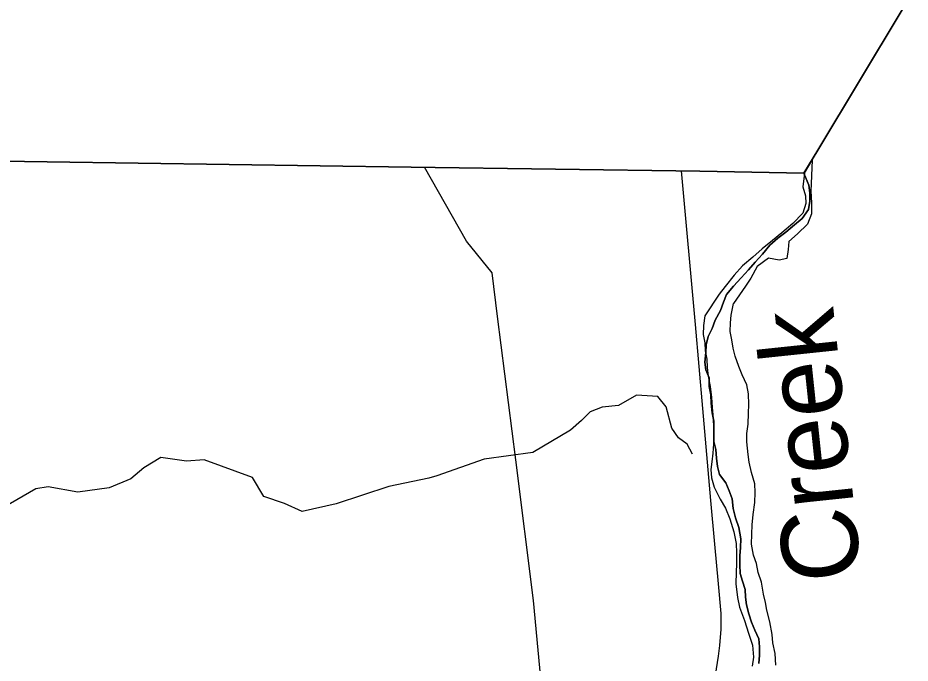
# Model space of a CAD drawing. Extents: x 1525783 to 1900577, y 218250 to 627376.
# Drawn here: x 1716711 to 1722538, y 499637 to 503848 of the extents above; entities that cross this region are included whole.
import ezdxf

# ---------------------------------------------------------------- set-up
doc = ezdxf.new("R2010")
doc.units = 0
for name, color, linetype in [('GM_X_Adjacent_County', 7, 'Continuous'), ('GM_X_County', 7, 'Continuous'), ('GM_X_Major_River', 7, 'Continuous'), ('GM_X_Major_River_Text', 7, 'Continuous'), ('GM_X_Minor_River', 7, 'Continuous'), ('GM_X_Rail_Line', 7, 'Continuous'), ('GM_X_State_Route', 7, 'Continuous'), ('GM_X_Township', 7, 'Continuous')]:
    doc.layers.add(name, color=color, linetype=linetype)

msp = doc.modelspace()

# ---------------------------------------------------------------- linework, layer by layer
at = {"layer": 'GM_X_Adjacent_County'}
for points in [[(1735942.3, 526251.7), (1733055.8, 521469.6), (1733029.3, 521425.7), (1732533.7, 520602.9), (1729525.6, 515601.5), (1727395.9, 512074.5), (1725220.4, 508448.9), (1721934.8, 502985.4), (1721843.8, 502834), (1721165.1, 502848), (1719280.1, 502874.9), (1716306.7, 502917.3), (1714432, 502944), (1711385.6, 502988.7), (1707042.7, 503052.5), (1704565.5, 503089.8), (1704436.7, 503091.7), (1698640.9, 503175.5)], [(1721549.6, 499634), (1721555.2, 499690), (1721554.6, 499744.2), (1721550.1, 499796.4), (1721523.6, 499851.3), (1721503, 499904), (1721484.5, 499958.6), (1721470.1, 500017.2), (1721463.5, 500067.5), (1721460.8, 500117.7), (1721442.3, 500172.3), (1721427.7, 500222.8), (1721425.2, 500279), (1721426.8, 500337.1), (1721430.3, 500391.2), (1721431.9, 500449.3), (1721419.9, 500521.8), (1721397.6, 500584.6), (1721383.3, 500647.1), (1721375, 500709.5), (1721356.4, 500762.1), (1721333.8, 500812.9), (1721293.3, 500868.1), (1721280.7, 500920.6), (1721274.2, 500974.9), (1721269.7, 501031.2), (1721255.2, 501083.7), (1721255.2, 501157.9), (1721256.8, 501216), (1721244.3, 501270.5), (1721238, 501334.8), (1721235.5, 501389), (1721225, 501443.4), (1721226.5, 501499.5), (1721203.9, 501550.3), (1721197.3, 501600.6), (1721203, 501664.6), (1721206.4, 501714.6), (1721219.8, 501768.4), (1721245.3, 501821.9), (1721264.8, 501875.5), (1721300.5, 501938.7), (1721319.9, 501992.3), (1721339.7, 502042.6), (1721385, 502097.6), (1721434.3, 502152.4), (1721481.6, 502203.2), (1721526.8, 502254.1), (1721574.1, 502307), (1721621.5, 502363.9), (1721674.7, 502410.6), (1721725.6, 502449.3), (1721782.8, 502497.9), (1721833.8, 502538.6), (1721875.3, 502597.7), (1721882.6, 502651.6), (1721884, 502705.6), (1721877.2, 502755.9), (1721843.8, 502834), (1721934.8, 502985.4), (1725220.4, 508448.9)]]:
    msp.add_lwpolyline(points, dxfattribs=at)
at = {"layer": 'GM_X_County'}
msp.add_lwpolyline([(1716306.7, 502917.3), (1719280.1, 502874.9), (1721165.1, 502848), (1721843.8, 502834), (1721877.2, 502755.9), (1721884, 502705.6), (1721882.6, 502651.6), (1721875.3, 502597.7), (1721833.8, 502538.6), (1721782.8, 502497.9), (1721725.6, 502449.3), (1721674.7, 502410.6), (1721621.5, 502363.9), (1721574.1, 502307), (1721526.8, 502254.1), (1721481.6, 502203.2), (1721434.3, 502152.4), (1721385, 502097.6), (1721339.7, 502042.6), (1721319.9, 501992.3), (1721300.5, 501938.7), (1721264.8, 501875.5), (1721245.3, 501821.9), (1721219.8, 501768.4), (1721206.4, 501714.6), (1721203, 501664.6), (1721197.3, 501600.6), (1721203.9, 501550.3), (1721226.5, 501499.5), (1721225, 501443.4), (1721235.5, 501389), (1721238, 501334.8), (1721244.3, 501270.5), (1721256.8, 501216), (1721255.2, 501157.9), (1721255.2, 501083.7), (1721269.7, 501031.2), (1721274.2, 500974.9), (1721280.7, 500920.6), (1721293.3, 500868.1), (1721333.8, 500812.9), (1721356.4, 500762.1), (1721375, 500709.5), (1721383.3, 500647.1), (1721397.6, 500584.6), (1721419.9, 500521.8), (1721431.9, 500449.3), (1721430.3, 500391.2), (1721426.8, 500337.1), (1721425.2, 500279), (1721427.7, 500222.8), (1721442.3, 500172.3), (1721460.8, 500117.7), (1721463.5, 500067.5), (1721470.1, 500017.2), (1721484.5, 499958.6), (1721503, 499904), (1721523.6, 499851.3), (1721550.1, 499796.4), (1721554.6, 499744.2), (1721555.2, 499690), (1721549.6, 499634)], dxfattribs=at)
at = {"layer": 'GM_X_Major_River'}
msp.add_line((1721847.3, 502835), (1721898, 502919.6), dxfattribs=at)
for points in [[(1721898, 502919.6), (1721889.4, 502716.4), (1721894.4, 502640.1), (1721893.5, 502569.9), (1721868.6, 502502.1), (1721801.7, 502438.8), (1721746.9, 502389.4), (1721742.3, 502337.3), (1721733.5, 502277.2), (1721683.2, 502265.9), (1721613.3, 502280.9), (1721538.5, 502225.7), (1721497.4, 502150), (1721462.7, 502096.3), (1721385.4, 501984.3)], [(1721847.3, 502835), (1721837.7, 502745.2), (1721855, 502686.8), (1721856.3, 502636.6), (1721837.5, 502574.7), (1721772.5, 502505.4), (1721699.6, 502446.2), (1721638.9, 502394.8), (1721572.1, 502341.6), (1721511.3, 502286.2), (1721442.4, 502229), (1721389.6, 502169.5), (1721330.5, 502096.1), (1721291.8, 502044.5)], [(1721291.8, 502044.5), (1721198.4, 501904.3), (1721187.6, 501840.3), (1721186.8, 501782.2), (1721198.2, 501728), (1721199.5, 501675.9), (1721210.9, 501621.6), (1721212.2, 501567.5), (1721219.5, 501509.3), (1721232.7, 501443), (1721239.8, 501370.8), (1721245, 501304.6), (1721252.1, 501234.4), (1721253.3, 501172.2), (1721254.7, 501120.1), (1721254, 501068), (1721249.3, 501008), (1721242.6, 500951.9), (1721236, 500899.9), (1721241.3, 500845.7), (1721258.5, 500785.4), (1721297.6, 500706.8), (1721332.9, 500648.3), (1721360, 500579.8), (1721387, 500493.3), (1721402.1, 500419), (1721403.3, 500356.9), (1721404.4, 500284.7), (1721401.7, 500230.6), (1721398.8, 500154.5), (1721409.7, 500066.2), (1721422.9, 500001.9), (1721455.9, 499915.4), (1721482.9, 499832.9), (1721507.9, 499754.4), (1721514.9, 499676.2), (1721506.2, 499618.2)], [(1721660.3, 499624.4), (1721657.3, 499700.6), (1721642.1, 499768.9), (1721636.8, 499823.1), (1721621.8, 499907.4), (1721602.7, 499981.8), (1721593.4, 500032), (1721580, 500088.3), (1721567, 500166.6), (1721545.8, 500228.9), (1721534.5, 500287.2), (1721515.1, 500341.5), (1721502, 500413.8), (1721504.8, 500477.9), (1721505.6, 500540), (1721512.4, 500608.1), (1721523.4, 500686.1), (1721526.2, 500750.2), (1721522.9, 500806.3), (1721501.8, 500880.7), (1721486.6, 500949), (1721481.3, 500999.2), (1721472.3, 501081.5), (1721470.9, 501135.6), (1721479.7, 501197.6), (1721482.6, 501267.7), (1721485.3, 501325.8), (1721482.1, 501394), (1721470.9, 501454.2), (1721441.7, 501518.7), (1721418.3, 501573.1), (1721395.1, 501639.5), (1721381.8, 501693.7), (1721374.5, 501747.9), (1721363.1, 501802.2), (1721365.8, 501858.2), (1721368.4, 501908.3), (1721385.4, 501984.3)]]:
    msp.add_lwpolyline(points, dxfattribs=at)
at = {"layer": 'GM_X_Minor_River'}
msp.add_line((1721847.3, 502835), (1721898.4, 502922), dxfattribs=at)
msp.add_lwpolyline([(1721117.7, 501001), (1721082.6, 501065.6), (1721025.1, 501108.5), (1720982, 501171.3), (1720943.9, 501310.2), (1720890.8, 501377.1), (1720750.8, 501385), (1720633.7, 501318.5), (1720527.4, 501307.9), (1720448.8, 501276.9), (1720391.9, 501221.6), (1720320.9, 501158.4), (1720074.5, 501011.5), (1719755.4, 500967.8), (1719447.5, 500859.8), (1719395.2, 500844.5), (1719134.1, 500790), (1718790, 500676.5), (1718569, 500627.4), (1718451.6, 500679.2), (1718318.1, 500725.1), (1718243.8, 500848.5), (1717929, 500963.1), (1717812.8, 500954.7), (1717644.9, 500979.1), (1717533.8, 500912.5), (1717448.6, 500839.5), (1717307.6, 500781.3), (1717102.9, 500754), (1716909.2, 500788.8), (1716828.9, 500773.9), (1716622.9, 500654.5)], dxfattribs=at)
at = {"layer": 'GM_X_Rail_Line'}
msp.add_lwpolyline([(1721267.1, 499559.7), (1721287.4, 499681.8), (1721296, 499752), (1721303.8, 499858.9), (1721303.8, 499961.9), (1721285.5, 500155.5), (1721263.2, 500413.3), (1721236.9, 500699.4), (1721183.8, 501299.8), (1721135.9, 501847), (1721046, 502849.2)], dxfattribs=at)
at = {"layer": 'GM_X_State_Route'}
msp.add_lwpolyline([(1720139.4, 499398.6), (1720078.3, 500046.7), (1719964, 500964.3), (1719843.5, 501898.9), (1719807.9, 502184.9), (1719641.5, 502390.4), (1719367.8, 502873.4)], dxfattribs=at)
at = {"layer": 'GM_X_Township'}
msp.add_lwpolyline([(1716306.7, 502917.3), (1719280.1, 502874.9), (1721165.1, 502848), (1721843.8, 502834), (1721877.2, 502755.9), (1721884, 502705.6), (1721882.6, 502651.6), (1721875.3, 502597.7), (1721833.8, 502538.6), (1721782.8, 502497.9), (1721725.6, 502449.3), (1721674.7, 502410.6), (1721621.5, 502363.9), (1721574.1, 502307), (1721526.8, 502254.1), (1721481.6, 502203.2), (1721434.3, 502152.4), (1721385, 502097.6), (1721339.7, 502042.6), (1721319.9, 501992.3), (1721300.5, 501938.7), (1721264.8, 501875.5), (1721245.3, 501821.9), (1721219.8, 501768.4), (1721206.4, 501714.6), (1721203, 501664.6), (1721197.3, 501600.6), (1721203.9, 501550.3), (1721226.5, 501499.5), (1721225, 501443.4), (1721235.5, 501389), (1721238, 501334.8), (1721244.3, 501270.5), (1721256.8, 501216), (1721255.2, 501157.9), (1721255.2, 501083.7), (1721269.7, 501031.2), (1721274.2, 500974.9), (1721280.7, 500920.6), (1721293.3, 500868.1), (1721333.8, 500812.9), (1721356.4, 500762.1), (1721375, 500709.5), (1721383.3, 500647.1), (1721397.6, 500584.6), (1721419.9, 500521.8), (1721431.9, 500449.3), (1721430.3, 500391.2), (1721426.8, 500337.1), (1721425.2, 500279), (1721427.7, 500222.8), (1721442.3, 500172.3), (1721460.8, 500117.7), (1721463.5, 500067.5), (1721470.1, 500017.2), (1721484.5, 499958.6), (1721503, 499904), (1721523.6, 499851.3), (1721550.1, 499796.4), (1721554.6, 499744.2), (1721555.2, 499690), (1721549.6, 499634)], dxfattribs=at)

# ---------------------------------------------------------------- texts
at = {"layer": 'GM_X_Major_River_Text'}
msp.add_text('Creek', height=500.01, rotation=95.99802, dxfattribs=at).set_placement((1722221.6, 500192.9))

doc.saveas('drawing.dxf')
